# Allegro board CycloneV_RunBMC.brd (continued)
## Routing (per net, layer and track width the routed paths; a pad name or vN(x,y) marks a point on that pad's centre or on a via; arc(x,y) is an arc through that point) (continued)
RMII_NIC_BMC_CRS_R_DV: length 4
  BOTTOM w0.112: RB191.1 56.29,4.41 56.43,4.27 56.91,4.27 57.18,4.01 JT3.216
RMII_NIC_BMC_RXD_0: length 36.7
  TOP w0.127: UT7.AD12 v1(37.18,16.81)
  L3-SIG w0.076: v1(59.92,4.76) 59.12,4.76 58.64,5.24 57.85,5.24 57.52,4.91 56.31,4.91 55.62,5.6 55.62,6.12 55,6.73 55,11.34 54.13,12.21 54.13,12.81 55.24,13.92 55.24,14.23 54.61,14.86 49.59,14.86 49.29,14.56 49.29,14.48 49.14,14.33 46.06,14.33 45.06,15.33 44.11,15.33 43.25,16.19 43.25,16.46 42.49,17.23 37.6,17.23 v1(37.18,16.81) 37.19,16.81
  BOTTOM w0.112: v1(59.92,4.76) 59.32,5.36 RB173.2
RMII_NIC_BMC_RXD_1: length 31.1
  TOP w0.127: v1(40.4,10.37) 40.4,10.9 40.1,11.21 39.58,11.21 UT7.AG5
  L3-SIG w0.076: v1(40.4,10.37) 40.82,9.96 41.44,9.96 45.72,5.67 45.72,5.05 46.3,4.47 46.45,4.47 47.21,3.71 47.21,2.55 48.13,1.63 58.26,1.63 59.37,2.74 59.37,3.88 59.61,4.12 v1(60.95,4.12)
  BOTTOM w0.112: RB172.2 61.72,5.76 61.72,4.98 61.51,4.78 61.41,4.78 60.95,4.32 v1(60.95,4.12)
RMII_NIC_BMC_RXD_R_0: length 4.4
  BOTTOM w0.112: JT3.228 60.18,2.84 60.31,2.97 60.31,5.74 RB173.1
RMII_NIC_BMC_RXD_R_1: length 4.5
  BOTTOM w0.112: JT3.230 60.68,3.03 60.55,3.16 60.55,4.96 60.95,5.36 60.95,5.81 RB172.1
RST_BMC_RSTBTN_OUT_N: length 33.5
  TOP w0.127: UT7.AF7 v1(38.78,12.81)
  L8-SIG w0.076: v1(38.78,12.81) 38.78,12.33 39.94,11.16 39.94,9.46 39.73,9.24 39.33,9.24 38.41,8.32 34.88,8.32 33.42,6.87 33.03,6.87 32.19,6.03 31.5,6.03 31.08,5.61 31.08,4.55 30.14,3.61 30.14,2.75 29.61,2.22 21.48,2.22 v1(20.41,3.28)
  BOTTOM w0.089: 39.52,12.07 v1(38.78,12.81)
  BOTTOM w0.112: RB139.2 41.41,11.97 39.62,11.97 39.52,12.07 ; JT3.76 20.32,1.71 20.32,2.78 20.41,2.88 v1(20.41,3.28)
RST_EMMC_SMC_R_N: length 8
  TOP w0.104: v1(9.98,30.47) 10.46,30 12.16,30 12.49,30.33 12.49,31.78 12.69,31.98 13.1,31.98 13.62,32.5 RT12.2
  BOTTOM w0.127: UB4.M5 v1(9.98,30.47)
RST_ESPI_RESET_BMC_N: length 20.7
  TOP w0.104: v1(44.7,5.52) 44.7,5.13 44.09,4.53 44.09,3.6 44.43,3.26 JT3.165
  TOP w0.127: v1(33.98,13.59) 33.98,13.61 UT7.Y8
  L3-SIG w0.076: v1(44.7,5.52) 44.7,6.23 41.71,9.21 40.76,9.21 40.75,9.23 37.69,9.23 37.59,9.33 37.59,9.76 37.38,9.96 37.08,9.96 36.24,10.8 35.5,10.8 35.15,11.15 35.15,11.38 34.89,11.64 34.44,11.64 33.98,12.1 v1(33.98,13.59)
RST_HPS_POR_M10_N: length 94.5
  TOP w0.104: v1(1.77,33.03) 2.38,33.03 2.53,32.88 ; 2.53,32.88 2.86,33.21 3.05,33.21 3.32,33.48 R4L128.2 ; 2.53,32.88 UT1.3
  TOP w0.127: UT4.A11 v1(53.88,24.44)
  L5-SIG w0.076: v1(47.75,49.26) 48.41,48.6 48.41,48.29 50.34,46.36 50.34,38.16 50.99,37.5 50.99,33.39 51.26,33.13 53.68,33.13 53.88,32.92 v1(53.88,24.44)
  L8-SIG w0.076: v1(1.77,33.03) 0.98,33.81 0.98,48.11 1.77,48.89 4.16,48.89 4.17,48.9 47.39,48.9 v1(47.75,49.26)
RST_HPS_POR_N: length 136.3
  TOP w0.104: v1(61.74,41.56) 63.62,41.56 63.72,41.66 JT1.7 ; v1(5.23,30.48) 5.23,29.48 5.07,29.33 R4L39.2 4.21,29.33 4.08,29.21 R4L40.2 4.07,28.61 R4L29.2
  TOP w0.127: UT7.H19 v1(23.58,23.21)
  L3-SIG w0.076: v1(61.74,41.56) 61.74,43.49 61.56,43.67 61.56,46.87 60.42,48.01 6.01,48.01 3.45,45.45 3.45,26.5 3.98,25.96 4.39,25.96 5.04,25.32 6.74,25.32 7.16,25.74 7.71,25.74 8.43,25.02 12.39,25.02 14.01,23.4 18.31,23.4 18.46,23.55 21.38,23.55 21.72,23.21 v1(23.58,23.21)
  L10-SIG w0.076: v1(5.23,30.48) 5.77,31.03 8,31.03 8.4,30.63 8.4,29.57 10.14,27.83 11.49,27.83 11.73,27.59 13.36,27.59 16.69,24.26 17.87,24.26 18.51,23.63 23.16,23.63 v1(23.58,23.21)
RST_HPS_POR_R1_N: length 1.6
  TOP w0.104: R4L29.1 2.38,29.14 2.53,29.3 UT1.4
RST_HPS_POR_R_N: length 1.8
  TOP w0.104: R4L39.1 4.64,30.54 4.39,30.79 3.96,30.79 3.83,30.67 UT1.6
RST_HPS_PORBTN__R_N: length 13.6
  BOTTOM w0.508: v1(2.3,36.05) 2.84,36.58 2.84,42.93 1.34,44.43 1.34,45.98 2.63,47.27 Q6A1.1
RST_HPS_RST_M10_N: length 77.7
  TOP w0.127: v1(54.88,24.49) 54.88,24.49 54.88,25.02 UT4.A10
  L5-SIG w0.076: v1(59.38,49.18) 60.57,47.99 60.57,40.42 59.51,39.35 58.24,39.35 56.48,37.6 56.48,37.24 54.88,35.64 v1(54.88,24.49)
  L8-SIG w0.076: v1(14.88,47.15) 14.88,47.53 15.46,48.11 48.96,48.11 49.57,48.72 58.92,48.72 v1(59.38,49.18)
  BOTTOM w0.112: UB1.3 13.59,48.63 13.73,48.77 14.14,48.77 14.45,48.47 14.84,48.47 RB21.2 14.93,47.19 v1(14.88,47.15)
RST_HPS_RST_N: length 30.6
  TOP w0.089: UT7.A23 17.62,26.01
  TOP w0.104: R7A4.2 9.2,41.37 v1(9.65,41.81) 9.19,41.81 9.08,41.92 J4.10 ; v1(13.07,34.93) 14.3,34.93 14.51,34.73 RT12.1 15.26,34.12 16.48,32.9 16.48,31.07 16.78,30.76 16.78,28.76 17.27,28.28 17.27,26.24 17.5,26.01 17.62,26.01
  L8-SIG w0.076: v1(9.65,41.81) 10.15,41.31 10.15,38.51 10.46,38.21 10.46,35.16 10.68,34.93 v1(13.07,34.93)
  BOTTOM w0.112: v1(9.65,41.81) 11.49,43.66 R7A2.2 RB36.2
RST_HPS_RST_R1_N: length 1.3
  BOTTOM w0.112: UB1.6 R7A2.1
RST_HPS_RST_R2_N: length 1.3
  BOTTOM w0.112: UB1.4 RB36.1
RST_HPS_RSTBTN__R_N: length 13.9
  TOP w0.104: v1(9.59,41.18) 10,40.77 10,38.89
  BOTTOM w0.112: v1(9.59,41.18) 9.24,41.53 9.24,42.6 11.22,44.58 11.22,46.16 12.29,47.22 UB1.1 11.96,48.16 11.7,48.42 R7A1.2 10.41,48.42 10.15,48.16 Q7A1.1
RST_PERSTL1_R: length 21.1
  TOP w0.127: UT7.W15 v1(33.18,20.01)
  L5-SIG w0.076: v1(33.18,20.01) 33.57,20.4 34.94,20.4 35.17,20.17 35.17,16.39 34.36,15.58 34.36,13.12 32.8,11.56 32.8,8.62 33.03,8.39 34.18,8.39 34.77,7.8 v1(34.77,7.7)
  BOTTOM w0.089: 36.49,7.65 36.49,7.72 36.13,8.08 35.15,8.08 v1(34.77,7.7)
  BOTTOM w0.112: RB177.1 36.49,7.65
RST_PLTRST_B_N: length 6
  BOTTOM w0.112: JT3.142 36.68,2.96 36.77,3.05 36.77,3.83 38.02,5.07 RB175.2 RB177.2
RST_PLTRST_MONITOR_N: length 35.7
  TOP w0.104: v1(31.34,7.22) 27.2,7.22 26.59,6.61 26.59,4.6 26.29,4.3 26,4.3 25.43,3.72 JT3.97
  TOP w0.127: UT7.AF21 v1(38.78,24.81)
  L5-SIG w0.076: v1(38.78,24.81) 38.78,23.91 38.37,23.5 38.37,19.72 37.59,18.94 37.59,11.84 36.75,11 36.75,8.62 36.59,8.46 36.59,7.19 35.95,6.55 34.1,6.55 33.81,6.84 31.57,6.84 31.34,7.07 v1(31.34,7.22)
RST_SMC_SMB_MUX_RST_N: length 38.7
  TOP w0.089: UT7.AH14 40.44,18.81
  TOP w0.104: v1(42.72,19.16) 41.64,19.16 41.36,19.44 RT59.1 41.34,19.72 40.44,18.81 ; JT3.101 26.43,2.92 26.66,3.15 26.66,3.6 26.79,3.72 v1(27.37,3.72)
  L5-SIG w0.076: v1(42.72,19.16) 41.85,18.29 41.85,14.76 43.2,13.42 43.2,12 42.79,11.6 42.79,8.06 42.11,7.37 42.11,6.47 41.62,5.99 37.8,5.99 36.76,4.95 34.92,4.95 34.59,4.62 34.59,4.2 34.87,3.92 34.87,2.9 34.48,2.51 28.56,2.51 27.65,3.43 27.65,3.45 v1(27.37,3.72)
RST_USBPHY_RESET_N: length 45
  TOP w0.104: v1(58.39,14.25) 58.39,14.18 58.05,13.85 57.99,13.85 RT91.2 58,13.62 U8A6.27
  TOP w0.127: UT7.C6 v1(19.58,12.01)
  L10-SIG w0.076: v1(50.65,11.43) 50.27,11.43 50.23,11.38 46.17,11.38 45.03,12.52 43.75,12.52 42.64,11.41 41.55,11.41 40.94,10.8 34.59,10.8 34.38,11.01 34.38,11.38 34.18,11.59 21.43,11.59 20.57,12.45 20.02,12.45 v1(19.58,12.01)
  BOTTOM w0.112: v1(58.39,14.25) 58.23,14.41 57.07,14.41 56.66,14 55.93,14 55.29,13.37 54.8,13.37 54.79,13.37 54.73,13.37 54.3,12.93 51.86,12.93 51.61,12.68 51.61,12.5 50.92,11.82 50.92,11.7 v1(50.65,11.43)
RST_USBPHY_USB2B_RESET_N: length 56.7
  TOP w0.104: EU12.27 60.94,21.48 v1(60.95,21.49)
  TOP w0.127: UT7.E4 v1(21.18,10.41)
  L10-SIG w0.076: v1(21.18,10.41) 21.18,10.67 20.8,11.05 20.8,11.38 20.59,11.59 19.45,11.59 19.23,11.81 19.23,15.46 19.35,15.58 21.33,15.58 21.8,15.11 22.05,15.11 23.09,14.07 23.09,13.61 23.44,13.27 23.97,13.27 24.28,12.96 35.26,12.96 36.3,13.99 38.99,13.99 39.24,13.75 39.84,13.75 40.33,14.24 42.5,14.24 42.69,14.05 48.66,14.05 49.47,14.86 55.54,14.86 58.38,17.7 58.38,17.93 60.95,20.51 v1(60.95,21.49)
  BOTTOM w0.112: R411.2 v1(60.95,21.49)
SGPIO_SMC_CPLD_CLK: length 60
  TOP w0.104: v1(6.09,3.95) 6.31,3.95 6.52,3.74 6.52,3.26 6.52,3.26 6.52,3.23 5.93,2.64 JT3.19
  TOP w0.127: v1(38.81,30.45) 38.78,30.42 38.78,29.61 UT7.AF27
  L8-SIG w0.076: v1(6.09,3.95) 5.8,3.95 5.59,3.73 5.08,3.73 4.43,4.39 4.43,5.5 4.92,6 6.05,6 7.46,7.41 7.46,8.75 7.66,8.94 7.66,15.2 11.27,18.81 11.27,20.22 13.86,22.81 13.86,23.88 15.82,25.84 18.28,25.84 18.46,26.02 23.41,26.02 24.99,27.59 25.39,27.59 25.62,27.82 25.62,29.04 25.77,29.19 28.67,29.19 29.05,29.57 29.05,30.05 29.97,30.97 32.91,30.97 33.53,31.58 34.99,31.58 35.44,31.13 38.13,31.13 v1(38.81,30.45)
SGPIO_SMC_CPLD_DIN: length 56.4
  TOP w0.104: v1(5.35,4.65) 5.15,4.65 4.82,4.32 4.82,2.99 4.93,2.88 JT3.15
  TOP w0.127: v1(38.78,28.83) 38.78,28.01 UT7.AF25
  L8-SIG w0.076: v1(38.78,28.83) 38.42,29.19 31.06,29.19 30.3,28.43 29.89,28.43 29.83,28.37 29.83,28.37 29.05,27.59 26.61,27.59 26.41,27.39 26.41,26.8 24.78,25.18 24.15,25.18 24,25.02 24,24.69 23.72,24.41 18.46,24.41 18.28,24.24 15.86,24.24 11.68,20.06 11.68,18.04 11.21,17.57 11.21,16.16 10.77,15.72 10.77,14.92 9.23,13.38 9.23,11.54 9.52,11.25 9.52,8.01 9.15,7.65 8.27,7.65 7.97,7.35 7.97,5.72 7.76,5.51 5.94,5.51 5.76,5.33 5.76,4.77 5.64,4.65 v1(5.35,4.65)
SGPIO_SMC_CPLD_DOUT: length 55.8
  TOP w0.104: JT3.17 5.43,2.88 5.08,3.23 5.08,3.89 v1(5.31,4.12)
  TOP w0.127: UT7.AF28 v1(37.95,30.44)
  L8-SIG w0.076: v1(37.95,30.44) 37.53,30.03 29.79,30.03 29.38,29.62 29.38,28.91 28.9,28.43 26.54,28.43 26.36,28.25 26.36,27.82 26.16,27.62 25.85,27.62 25.57,27.34 25.57,26.75 24.75,25.93 24.19,25.93 23.97,25.71 23.97,25.48 23.7,25.2 16.54,25.2 11.47,20.14 11.47,18.73 10.37,17.62 10.37,14.81 8.65,13.09 8.65,10.78 9.27,10.16 9.27,8.05 9.07,7.85 8.19,7.85 6.06,5.72 5.12,5.72 4.83,5.42 4.83,4.61 v1(5.31,4.12)
SGPIO_SMC_CPLD_LD_N: length 61.9
  TOP w0.104: v1(4.01,4.68) 4.06,4.73 4.24,4.73 4.43,4.54 JT3.13
  TOP w0.114: UT7.AG28 39.77,30.01 40.13,30.36 40.13,31.98 39.72,32.39 36.44,32.39 v1(35.88,31.83)
  L8-SIG w0.076: v1(35.88,31.83) 35.45,32.26 33.46,32.26 32.47,31.27 29.86,31.27 28.59,30 24.9,30 24.78,29.89 24.78,27.79 23.79,26.8 21.28,26.8 21.27,26.81 16.5,26.81 13.61,23.92 13.61,22.87 11.07,20.33 11.07,18.95 6.75,14.64 6.75,9.12 6.61,8.98 6.61,6.97 5.85,6.2 4.69,6.2 4.01,5.52 v1(4.01,4.68)
SMB_BATPAK_CLK: length 38.8
  TOP w0.089: 40.73,28.71 40.44,28.41 UT7.AH26
  TOP w0.104: 40.73,28.71 40.76,28.73 41.48,28.73 41.55,28.66 RT33.1 41.52,28.69 41.52,29.27 v1(41.83,29.57) ; v1(50.37,5.41) 50.37,4.92 49.93,4.48 JT3.187
  L3-SIG w0.076: v1(41.83,29.57) 41.86,29.6 43.07,29.6 44.49,28.17 v1(48.02,28.17)
  L8-SIG w0.076: v1(48.02,28.17) 48,28.17 47.59,27.77 47.59,22.52 48.39,21.72 48.39,19.68 49.57,18.5 49.57,17.76 48.74,16.92 48.74,12.81 48.28,12.35 48.28,7.67 50.24,5.7 50.24,5.69 50.31,5.62 50.31,5.47 v1(50.37,5.41)
SMB_BATPAK_DATA: length 43.7
  TOP w0.104: v1(50.41,4.43) 50.82,4.02 50.82,3.2 50.43,2.81 JT3.189
  TOP w0.127: UT7.AC22 v1(36.4,25.63)
  L3-SIG w0.076: v1(48.05,27.62) 47.57,27.62 47.31,27.87 44.06,27.87 42.95,26.76 37.08,26.76 36.4,26.08 v1(36.4,25.63)
  L8-SIG w0.076: v1(50.41,4.43) 50.76,4.77 50.76,5.57 50.59,5.73 50.59,6.56 50.14,7.01 50.14,8.32 50.27,8.45 50.27,10.52 49.36,11.43 49.36,12.64 49.04,12.96 49.04,16.64 49.88,17.48 49.88,18.62 48.61,19.89 48.61,21.85 47.9,22.56 47.9,27.08 48.05,27.23 v1(48.05,27.62)
  BOTTOM w0.089: v1(36.4,25.63) 36.76,25.99 37.53,25.99 37.73,25.8 RT137.1
SMB_BMC2BMC_CLK: length 32.2
  TOP w0.104: v1(48.76,4.91) 48.4,4.55 48.4,4.15 48.74,3.82 48.74,3 48.43,2.69 JT3.181
  TOP w0.127: UT7.AG16 v1(39.56,20.03)
  L8-SIG w0.076: v1(47.75,20.43) 46.81,19.49 46.81,14.31 46.21,13.71 46.21,11.41 v1(46.65,10.97) 46.88,10.74 46.88,8.03 48.76,6.15 v1(48.76,4.91)
  L10-SIG w0.076: v1(39.56,20.03) 39.88,20.35 42.51,20.35 42.79,20.63 47.17,20.63 47.37,20.43 v1(47.75,20.43)
  BOTTOM w0.112: R2A21.1 47.08,11.7 46.87,11.49 46.32,11.49 46.15,11.31 RB148.1 46.64,10.98 v1(46.65,10.97)
SMB_BMC2BMC_DATA: length 32.1
  TOP w0.089: 40.73,17.56 40.33,17.56 UT7.AH12
  TOP w0.104: JT3.183 48.93,2.87 48.97,2.91 48.97,3.25 v1(49.35,3.64) ; v1(48.52,18.23) 48.52,18.17 48.06,17.71 45.57,17.71 45.14,18.14 44.57,18.14 43.99,17.56 43.33,17.56 42.98,17.2 41.52,17.2 41.26,17.47 RT70.1 40.73,17.56
  L8-SIG w0.076: v1(48.52,18.23) 48.37,18.08 48.37,12.92 48.06,12.62 48.06,12.6 47.85,12.39 47.85,11.33 47.34,10.83 47.34,8.13 49.17,6.3 49.17,4.38 49.35,4.21 v1(49.35,3.64)
  BOTTOM w0.112: R2A22.2 48.28,17.6 48.52,17.84 v1(48.52,18.23)
SMB_BMC_RSSD_7_0_CLK: length 22.5
  TOP w0.089: UT7.AG8 39.54,13.65 40.03,13.65 40.14,13.54 40.73,13.54
  TOP w0.104: v1(41.79,11.03) 41.79,11.63 41.66,11.76 41.66,13.7 41.47,13.89 RT93.1 41.23,13.89 40.89,13.54 40.73,13.54 ; JT3.123 31.93,3.11 v1(31.96,3.14)
  L8-SIG w0.076: v1(41.79,11.03) 41.83,10.99 41.83,8.69 40.71,7.57 40.26,7.57 40.18,7.65 37.62,7.65 36.05,6.08 34.59,6.08 33.6,5.09 32.66,5.09 32.35,4.77 32.35,4.34 32.37,4.32 32.37,3.55 v1(31.96,3.14)
SMB_BMC_RSSD_7_0_DATA: length 23.9
  TOP w0.104: RT114.1 32.58,5.97 v1(32.02,5.42) 32.02,5.03 32.05,5.01 32.05,4.65 32.38,4.32 32.38,3.23 32.43,3.17 JT3.125
  TOP w0.127: UT7.AG13 39.58,18.41 v1(39.59,18.41)
  L5-SIG w0.076: v1(32.02,5.42) 33.86,5.42 34.34,5.9 36.3,5.9 37.28,6.88 37.28,7.49 38.4,8.62 38.4,11.49 39.16,12.25 39.16,17.99 v1(39.59,18.41)
SMB_C5_M10_CLK: length 20.4
  TOP w0.104: UT4.H15 49.39,31.53 48.18,31.53 47.87,31.22 47.87,30.49 47.52,30.13 RT49.1 46.96,25.81 46.8,25.66 v1(45.26,25.66) ; RT68.2 43.1,18.27 43.25,18.12 v1(43.63,18.12)
  L5-SIG w0.114: v1(45.26,25.66) 45.41,25.66 45.67,25.4 45.67,23.25 43.93,21.52 43.93,18.42 v1(43.63,18.12)
SMB_C5_M10_DATA: length 2.9
  TOP w0.104: UT4.H16 46.97,32.02 RT44.2 RT47.1
SMB_C5_M10_R_CLK: length 1.4
  TOP w0.089: UT7.AH13 40.24,18.27 40.73,18.27
  TOP w0.104: 40.73,18.27 40.84,18.27 40.85,18.27 RT68.1
SMB_C5_M10_R_DATA: length 24.5
  TOP w0.104: v1(45.52,31.6) 45.66,31.6 RT44.1
  TOP w0.127: UT7.W14 v1(33.18,18.41)
  L8-SIG w0.076: v1(33.18,18.41) 33.6,18.83 35.65,18.83 36.14,19.31 38.93,19.31 39.19,19.57 39.19,20.18 39.57,20.55 40.23,20.55 41.45,21.77 44.12,21.77 45.67,23.32 45.67,31.49 45.55,31.6 v1(45.52,31.6)
SMB_HOST_LVC3_CLK: length 27.8
  TOP w0.127: UT7.U14 v1(31.58,18.41)
  L5-SIG w0.076: v1(33.29,4.53) 32.78,5.04 32.21,5.04 31.29,4.12 29.41,4.12 28.8,4.73 28.79,4.73 28.56,4.96 28.56,5.78 30.12,7.34 30.12,7.64 30.37,7.89 30.37,11.64 31.97,13.24 31.97,15.27 32.53,15.83 32.53,16.36 32.76,16.59 32.76,18.64 32.6,18.8 31.97,18.8 v1(31.58,18.41)
  BOTTOM w0.112: RB190.1 33.39,5.06 33.29,4.96 v1(33.29,4.53) 33.85,4.53 34.61,3.77 34.61,3.07 34.68,3 JT3.134
SMB_HOST_LVC3_DATA: length 25.1
  TOP w0.089: 40.73,14.38 40,14.38 39.95,14.43 v1(39.58,14.43)
  TOP w0.104: RT90.1 41.62,15.02 40.99,14.38 40.73,14.38
  TOP w0.127: UT7.AG9 39.56,14.43 v1(39.58,14.43)
  L8-SIG w0.076: v1(39.58,14.43) 39.58,13.76 39.97,13.37 41.32,13.37 41.52,13.16 41.52,11.39 41.41,11.27 41.41,10.82 41.59,10.63 41.59,8.99 v1(40.56,7.96)
  BOTTOM w0.112: v1(40.56,7.96) 40.06,7.96 39.67,8.34 34.69,8.34 34.41,8.05 34.41,7.7 33.95,7.24 33.95,6.56 34.26,6.26 34.26,4.47 34.37,4.35 34.37,4.35 34.85,3.87 34.85,3.21 35.18,2.88 JT3.136
SMB_HSBP_LVC3_CLK: length 35.6
  TOP w0.089: 40.73,14.84 v1(40.58,14.84) 40.55,14.81 UT7.AH9
  TOP w0.104: RT88.1 41.29,15.52 41.12,15.36 41.12,15.01 40.96,14.84 40.73,14.84
  L8-SIG w0.076: v1(16.63,3.58) 17.02,3.58 17.04,3.6 19.28,3.6 20.02,4.34 20.45,4.34 20.91,4.79 20.91,5.15 21.12,5.36 21.65,5.36 23.87,7.57 24.71,7.57 26.36,9.23 28.7,9.23 29.44,9.97 30.13,9.97 30.42,10.26 30.42,10.56 30.63,10.77 30.91,10.77 31.16,11.02 31.16,11.33 32.38,12.55 33.09,12.55 33.67,13.13 34.03,13.13 36.39,15.49 36.39,16.08 36.68,16.37 39.84,16.37 40.07,16.13 40.07,15.35 v1(40.58,14.84)
  BOTTOM w0.112: JT3.60 16.18,2.75 16.63,3.2 v1(16.63,3.58)
SMB_HSBP_LVC3_DATA: length 42.3
  TOP w0.127: UT7.AE15 v1(37.98,20.01)
  L8-SIG w0.076: v1(37.98,20.01) 37.41,20.58 36.11,20.58 35.81,20.27 35.81,19.82 35.31,19.32 31.81,19.32 31.16,18.67 31.16,15.02 30.91,14.77 30.63,14.77 30.37,14.51 30.37,14.2 30.14,13.98 29.76,13.98 29.41,13.62 29.41,13.49 28.7,12.78 22.62,12.78 22.22,12.38 19.43,12.38 19.22,12.16 19.22,8.73 18.9,8.41 18.43,8.41 16.81,6.79 16.81,6.05 v1(16.17,5.42)
  BOTTOM w0.089: v1(37.98,20.01) 38.35,20.38 40.61,20.38 40.73,20.26 40.73,20.12 40.73,20.12
  BOTTOM w0.112: JT3.62 16.68,2.9 16.94,3.16 16.94,3.28 17.21,3.56 17.21,4.2 16.73,4.68 16.53,4.68 16.17,5.03 v1(16.17,5.42) ; RB106.1 40.85,19.84 40.76,19.93 40.76,20.09 40.73,20.12
SMB_INTERNAL_CLK: length 165.1
  TOP w0.104: EUT2.3 5.88,8.12 v1(6.22,7.79) ; EUT3.23 14.48,11.14 14.45,11.18 v1(14.45,11.25) ; JT1.5 62.45,44.98 62.24,45.19 v1(61.99,45.19) ; v1(11.42,12.37) 11.69,12.1 12.22,12.1 12.31,12.19 EUT1.19 ; v1(45.74,15.7) 45.74,14.46 45.64,14.36 45.23,14.36 RT92.1 45.15,14.28 R434.1
  L5-SIG w0.076: v1(11.42,12.37) 12.41,11.38 12.41,11.21 12.77,10.86 14.06,10.86 v1(14.45,11.25)
  L5-SIG w0.114: v1(45.74,15.7) 45.99,15.96 45.99,18.43 v1(44.65,19.77)
  L8-SIG w0.076: v1(44.65,19.77) 44.65,20.68 46.45,22.48 46.45,27.95 49.68,31.17 49.68,39.15 50.56,40.04 59.86,40.04 60.37,40.54 60.37,41.33 61.99,42.96 v1(61.99,45.19) 61.99,45.93 61.74,46.18 50.64,46.18 49.4,44.94 44.9,44.94 44.39,45.45 44.39,46.36 43.68,47.07 16.55,47.07 15.28,45.81 15.28,33.18 16.17,32.29 16.17,31.43 16.78,30.82 16.78,30.29 16.4,29.91 16.4,27.1 13.4,24.1 13.4,23.09 12.29,21.98 7.33,21.98 5.77,20.41 5.77,15.41 4.29,13.92 4.29,9.53 5.66,8.16 5.84,8.16 v1(6.22,7.79)
  L10-SIG w0.076: v1(11.42,12.37) 10.89,12.37 9.87,11.36 9.87,9.77 9.15,9.05 8.09,9.05 7.82,9.32 6.97,9.32 6.22,8.57 v1(6.22,7.79)
  BOTTOM w0.112: v1(44.65,19.77) 44.65,20.74 43.81,21.57 42.72,21.57 42.61,21.47 RB98.2
SMB_INTERNAL_CLK_R2: length 3.7
  TOP w0.104: EU5C1.4 48.49,11.89 48.15,12.22 47.92,12.22 47.8,12.35 47.39,12.35 47.01,12.73 47.01,12.74 46.61,13.14 46.42,13.14 R434.2
SMB_INTERNAL_DATA: length 166.4
  TOP w0.104: v1(62.45,45.52) JT1.6 ; R435.1 RT97.1 RT95.2 46.22,12.68 46.32,12.58 v1(46.63,12.58) ; EUT3.22 14.88,11.1 15.02,11.23 v1(15.02,11.24) ; EUT1.20 12.81,12.19 12.45,11.84 v1(11.4,11.84) ; EUT2.2 5.23,8.07 5.52,7.78 v1(5.68,7.78)
  L5-SIG w0.076: v1(11.4,11.84) 12.62,10.62 14.39,10.62 v1(15.02,11.24)
  L8-SIG w0.076: v1(46.63,12.58) 46.63,12.95 46.6,12.98 46.6,13.11 47.13,13.64 47.13,19.2 48.13,20.2 48.13,21.65 47.29,22.48 47.29,28.33 49.96,30.99 49.96,38.28 50.72,39.05 59.45,39.05 60.7,40.29 60.7,41.2 62.45,42.96 v1(62.45,45.52) 62.45,45.76 61.83,46.39 50.56,46.39 49.34,45.17 45,45.17 44.62,45.55 44.62,46.44 43.78,47.27 16.46,47.27 15.08,45.9 15.08,33.08 15.97,32.19 15.97,31.35 16.58,30.74 16.58,30.37 16.2,29.99 16.2,27.18 13.2,24.19 13.2,23.18 12.2,22.18 7.25,22.18 5.57,20.5 5.57,15.5 4.06,13.98 4.06,9.47 5.68,7.85 v1(5.68,7.78)
  L10-SIG w0.076: v1(5.68,7.78) 5.66,7.8 5.66,8.35 6.87,9.57 8,9.57 8.27,9.3 9.05,9.3 9.59,9.84 9.59,11.37 10.98,12.76 11.72,12.76 11.83,12.65 11.83,11.97 11.7,11.84 v1(11.4,11.84)
SMB_INTERNAL_DATA_R2: length 1
  TOP w0.104: EU5C1.5 47.6,11.35 47.49,11.46 R435.2
SMB_INTERNAL_R_CLK: length 3.3
  TOP w0.127: UT7.AF17 v1(38.78,21.61)
  BOTTOM w0.089: 40.73,21.19 39.41,21.19 39,21.61 v1(38.78,21.61)
  BOTTOM w0.112: RB98.1 41.01,21.47 40.73,21.19
SMB_INTERNAL_R_DATA: length 18.9
  TOP w0.104: v1(44.98,17.76) 44.98,17.3 45.01,17.27 45.01,16.19 44.68,15.86 44.68,13.11 RT95.1
  TOP w0.127: UT7.V13 v1(32.38,17.61)
  L3-SIG w0.076: v1(44.98,17.76) 44.6,17.76 44.58,17.73 43.38,17.73 43.08,18.03 42,18.03 41.98,18.01 33.04,18.01 32.63,17.61 v1(32.38,17.61)
SMB_IPMB_LVC3_CLK: length 18.1
  TOP w0.127: v1(40.35,12.81) 39.98,13.18 UT7.AH7
  L5-SIG w0.076: v1(32.76,3.92) 33.22,3.92 33.68,4.37 33.68,4.89 34.43,5.64 36.38,5.64 37.54,6.8 37.54,7.4 39.19,9.05 39.19,11.64 v1(40.35,12.81)
  BOTTOM w0.089: 40.73,12.43 v1(40.35,12.81)
  BOTTOM w0.112: JT3.128 33.18,3.81 33.07,3.92 v1(32.76,3.92) ; RB138.1 40.79,12.38 40.73,12.43
SMB_IPMB_LVC3_DATA: length 28.5
  TOP w0.127: UT7.AF13 38.78,18.41 v1(38.8,18.41)
  L5-SIG w0.076: v1(34.15,3.69) 34.15,3.74 33.92,3.98 33.92,4.79 34.54,5.42 36.53,5.42 37.78,6.67 37.78,7.19 38.47,7.88 39.34,7.88 39.97,8.51 39.97,11.79 40.4,12.22 40.99,12.22 41.34,12.58 41.34,13.06 41.07,13.34 40.43,13.34 40.02,13.75 40.02,18.65 39.77,18.9 39.29,18.9 v1(38.8,18.41)
  BOTTOM w0.089: 40.73,17.46 40.25,17.46 40,17.71 39.5,17.71 v1(38.8,18.41)
  BOTTOM w0.112: 40.73,17.46 RB116.1 ; JT3.130 33.68,3.6 33.75,3.66 34.13,3.66 v1(34.15,3.69)
SMB_PCIE_LVC3_CLK: length 57.5
  TOP w0.104: v1(53.59,4.93) 53.97,4.55 53.97,3.44 54.43,2.98 JT3.205
  TOP w0.127: UT7.U13 v1(31.58,17.61)
  L3-SIG w0.076: v1(31.58,17.61) 32,17.19 32,16.57 32.15,16.41 34.84,16.41 36.4,14.86 39.88,14.86 40.2,15.18 41.03,15.18 42.3,13.91 44.48,13.91 45.1,13.29 50.13,13.29 50.46,13.62 51.45,13.62 51.59,13.48 51.59,11.27 51.2,10.88 51.2,8.95 49.37,7.12 49.37,4.7 49.8,4.27 49.8,3.03 49.9,2.93 51.56,2.93 51.81,3.18 51.81,4.83 52.14,5.16 52.98,5.16 53.21,4.93 v1(53.59,4.93)
  BOTTOM w0.089: v1(31.58,17.61) 31.93,17.96 33.22,17.96 33.53,18.26 33.53,20.05 33.83,20.36 34.92,20.36 35.67,19.61 37.28,19.61 37.61,19.95 37.61,20.13 37.9,20.43 38.09,20.43 38.37,20.71 38.37,20.9 38.63,21.16 39.09,21.16 39.57,20.68 40.73,20.68
  BOTTOM w0.112: 40.73,20.68 40.79,20.68 41.08,20.39 RB102.1
SMB_PCIE_LVC3_DATA: length 31.1
  TOP w0.104: JT3.207 54.93,2.8 54.2,3.53 54.2,4.58 v1(54.55,4.93)
  TOP w0.127: UT7.AH8 40.19,14.01 40.25,13.95 40.46,13.95 40.5,13.9 40.52,13.9 v1(40.53,13.9)
  L3-SIG w0.089: v1(54.16,13.36) 54.16,13.38
  L5-SIG w0.076: v1(54.55,4.93) 54.17,5.32 54.17,6.08 53.47,6.78 53.47,10.2 53.18,10.5 53.18,12.38 v1(54.16,13.36)
  L10-SIG w0.076: v1(40.53,13.9) 40.9,13.9 41.03,13.77 49.6,13.77 50.41,14.59 52.91,14.59 54.14,13.36 v1(54.16,13.36)
  BOTTOM w0.089: 40.73,13.69 v1(40.53,13.9)
  BOTTOM w0.112: 40.73,13.69 40.82,13.61 RB133.1
SMB_PMBUS_LVC3_CLK: length 44.9
  TOP w0.104: JT3.47 12.93,4.14 13.26,4.48 13.45,4.48 v1(13.46,4.49)
  TOP w0.127: UT7.Y13 v1(33.98,17.61)
  L8-SIG w0.076: v1(13.46,4.49) 13.48,4.51 13.48,4.69 13.6,4.81 15.51,4.81 15.72,4.6 16.72,4.6 17.28,5.16 18.07,5.16 18.55,5.65 18.55,6.59 18.85,6.89 20.44,6.89 20.75,7.19 20.75,10.62 20.95,10.83 23.36,10.83 24.61,12.07 29.23,12.07 30.12,12.96 30.96,12.96 31.16,13.16 31.16,13.77 31.74,14.36 31.74,15.05 32.28,15.58 32.28,16.09 32.8,16.62 32.8,17 33.03,17.23 33.6,17.23 v1(33.98,17.61)
  BOTTOM w0.112: v1(33.98,17.61) 34.38,18.01 34.92,18.01 36.26,19.36 40.28,19.36 40.86,18.77 42.55,18.77 42.56,18.77 42.94,18.77 43.1,18.93 43.1,19.32 43.1,19.32 43.1,19.55 43,19.65 RB104.1
SMB_PMBUS_LVC3_DATA: length 38.8
  TOP w0.104: v1(13.42,3.92) 13.42,3.54 13.23,3.35 13.23,2.9 13.43,2.7 JT3.49 ; RT72.1 40.73,16.62 40.11,15.99 v1(39.6,15.99) UT7.AG11
  L8-SIG w0.076: v1(13.42,3.92) 13.42,3.9 13.68,3.64 14.87,3.64 15.19,3.32 15.19,3.12 15.63,2.69 18.88,2.69 20.14,3.94 21.06,3.94 22.04,4.92 22.04,5.41 23.8,7.17 24.89,7.17 26.16,8.45 27.73,8.45 29.03,8.45 29.83,9.25 30.13,9.25 31.22,10.33 31.22,10.56 31.43,10.77 31.69,10.77 31.95,11.03 31.95,11.44 32.66,12.15 33.06,12.15 33.8,12.89 34.9,12.89 35.59,13.57 35.59,14.31 36.86,15.57 39.18,15.57 v1(39.6,15.99)
SMB_RSSD_15_8_CLK: length 53.3
  TOP w0.089: 40.73,29.67 40.44,29.67 UT7.AH27
  TOP w0.104: 40.73,29.67 v1(41.12,29.67) 41.32,29.67 41.55,29.9 RT23.1
  L8-SIG w0.076: v1(41.12,29.67) 41.47,29.32 41.47,28.2 41.23,27.96 40.8,27.96 40.74,28.02 38.8,28.02 38.42,27.63 36.22,27.63 36.01,27.43 36.01,26.98 35.81,26.78 35.44,26.78 35.15,26.49 35.15,26.19 34.65,25.7 27.74,25.7 27.2,25.15 27.2,24.57 27.02,24.39 26.51,24.39 25.57,23.44 25.57,19.79 25.11,19.33 23.29,19.33 20.41,16.46 20.16,16.46 19.96,16.26 19.96,15.78 19.81,15.63 18.95,15.63 18.89,15.56 17.53,15.56 17.24,15.27 17.24,12.83 15.72,11.31 15.72,9.44 15.35,9.08 15.35,7.54 14.75,6.94 13.48,6.94 12.91,6.37 12.91,3.77 13.56,3.13 v1(13.66,3.13)
  BOTTOM w0.112: JT3.50 13.65,1.6 13.65,3.12 v1(13.66,3.13)
SMB_RSSD_15_8_DATA: length 52.8
  TOP w0.104: RT35.1 41.22,28.15 41.07,28.3 v1(41.07,28.35)
  TOP w0.127: UT7.AG25 39.55,27.98 40.7,27.98 v1(41.07,28.35)
  L8-SIG w0.076: v1(41.07,28.35) 38.13,28.35 38.11,28.37 35.85,28.37 35.17,27.69 35.17,27.01 34.97,26.81 33.02,26.81 32.78,26.57 32.78,26.2 32.51,25.92 27.1,25.92 26.34,25.16 26.34,24.64 25.27,23.58 25.01,23.58 24.78,23.35 24.78,19.86 24.48,19.55 23.22,19.55 20.61,16.93 20.21,16.93 19.73,16.45 17.42,16.45 15.97,15.01 15.97,13.82 15.44,13.29 15.44,10.98 14.75,10.29 13.21,10.29 12.24,9.33 12.24,7.31 12.52,7.04 12.52,5.52 12.37,5.37 v1(12.37,4.98)
  BOTTOM w0.112: JT3.48 13.18,3.58 13.17,3.6 13.17,3.61 13.02,3.75 13.02,4.33 v1(12.37,4.98)
SMB_SENSOR_FRU_CLK: length 2.3
  BOTTOM w0.112: R2A21.2 46.2,12.78 46.52,13.1 UB5.6
SMB_SENSOR_FRU_DAT: length 1.9
  BOTTOM w0.112: R2A22.1 47.28,13.24 47.17,13.35 UB5.5
SMB_SMLINK0_LVC3_CLK: length 45.3
  TOP w0.089: v1(39.58,15.21) 40.68,15.21 40.73,15.27
  TOP w0.104: RT86.1 41.32,16.06 40.89,15.63 40.89,15.42 40.73,15.27
  TOP w0.127: UT7.AG10 v1(39.58,15.21)
  L8-SIG w0.076: v1(39.58,15.21) 40.1,14.69 40.1,14.55 40.21,14.43 40.81,14.43 41.85,13.39 41.85,11.89 42.69,11.05 42.69,8.64 41.98,7.93 41.41,7.93 40.75,7.27 40.15,7.27 40,7.42 37.86,7.42 36.23,5.8 34.72,5.8 33.94,5.02 33.94,4.42 33.18,3.66 33.18,2.76 32.39,1.97 15.58,1.97 14.8,2.75 v1(14.8,3.16)
  BOTTOM w0.112: JT3.54 14.68,3.03 v1(14.8,3.16)
SMB_SMLINK0_LVC3_DATA: length 42.3
  TOP w0.127: UT7.AF15 v1(38.78,20.01)
  L8-SIG w0.076: v1(38.78,20.01) 38.36,19.59 35.99,19.59 35.45,19.06 32.23,19.06 32,18.83 32,15.86 31.51,15.37 31.51,14.56 30.96,14 30.63,14 30.42,13.79 30.42,13.51 30.14,13.24 29.74,13.24 28.92,12.43 24.56,12.43 23.73,11.6 20.13,11.6 19.96,11.44 19.96,7.5 19.75,7.3 17.71,7.3 17.06,6.64 17.06,5.31 16.61,4.86 15.87,4.86 15.43,5.29 v1(15.39,5.29)
  BOTTOM w0.089: 40.73,19.33 40.43,19.64 39.15,19.64 v1(38.78,20.01)
  BOTTOM w0.112: v1(15.39,5.29) 15.36,5.26 15.36,4.96 15.44,4.88 15.44,3.71 15.21,3.49 15.21,2.92 15.18,2.89 JT3.56 ; 40.73,19.33 RB109.1
SMB_SW2BMC_CLK_DBG_HOOK8: length 29
  TOP w0.089: UT7.D12 21.18,17.61 22.24,17.61 23.01,16.85 23.01,15.35 v1(22.85,15.19)
  TOP w0.104: JT3.135 34.93,2.88 34.73,3.08 34.73,3.08 34.66,3.15 34.66,3.16 34.63,3.19 34.63,3.68 34.99,4.05 35.51,4.05 35.6,4.14 v1(35.6,4.53) 35.6,4.9 35.44,5.06 35.43,5.06 35.15,5.34 RT135.1
  L3-SIG w0.076: v1(22.85,15.19) 22.9,15.19 23.3,14.79 23.69,14.79 23.95,14.53 23.95,14.35 24.27,14.03 24.45,14.03 24.76,13.72 24.76,13.53 25.1,13.19 27.83,13.19 29.33,11.69 29.33,7.93 30.91,6.36 31.64,6.36 32.76,5.24 35.27,5.24 35.6,4.9 v1(35.6,4.53)
SMB_SW2BMC_DATA_DBG_HOOK9: length 32
  TOP w0.089: UT7.C12 20.37,16.82 21.84,16.82 22.57,16.08 v1(22.57,15.93)
  TOP w0.104: JT3.137 35.43,2.71 34.89,3.25 34.89,3.26 34.87,3.28 34.87,3.57 35.12,3.82 35.84,3.82 36.14,4.12 v1(36.14,4.5) 36.14,4.98 35.78,5.34 RT136.1
  L3-SIG w0.076: v1(22.57,15.93) 22.57,15.55 22.5,15.47 22.5,14.86 23.34,14.03 23.65,14.03 23.95,13.74 23.95,13.55 24.71,12.78 27.4,12.78 28.87,11.31 28.87,7.04 29.69,6.23 29.69,4.44 29.88,4.24 31.68,4.24 32.35,4.91 33.5,4.91 34.38,4.02 35.65,4.02 v1(36.14,4.5)
SMB_TEMP_SENSOR_LVC3_CLK: length 50.9
  TOP w0.104: JT3.53 14.43,2.88 14.42,2.89 14.42,3.57 14.42,3.57 v1(14.42,4.15) ; v1(43.69,16.35) 43.62,16.28 43.62,16.1 43.62,16.1 43.62,14.4 43.29,14.07 UT10.2
  TOP w0.127: UT7.AA13 v1(34.78,17.61)
  L8-SIG w0.076: v1(34.78,17.61) 34.38,17.22 34.38,16.7 34.1,16.41 32.96,16.41 32.76,16.21 32.76,14.99 32.56,14.79 32.18,14.79 31.97,14.58 31.97,13.44 31.27,12.74 30.46,12.74 29.48,11.77 25.06,11.77 24.74,11.44 24.74,11.06 24.45,10.77 24.23,10.77 24.02,10.56 24.02,10.31 23.67,9.97 21.83,9.97 21.54,9.68 21.54,7.51 20.47,6.43 20.02,6.43 17.91,4.32 15.39,4.32 15.18,4.53 14.79,4.53 v1(14.42,4.15)
  BOTTOM w0.112: v1(43.69,16.35) 43.94,16.59 44.27,16.59 44.57,16.9 44.57,18.4 44.14,18.83 44.14,19.44 43.87,19.7 RB105.1 43.38,19.5 43.38,18.73 43.15,18.5 40.68,18.5 40.65,18.54 40.64,18.54 40.61,18.56 40.59,18.56 40.04,19.11 36.34,19.11 34.84,17.61 v1(34.78,17.61)
SMB_TEMP_SENSOR_LVC3_DATA: length 48.1
  TOP w0.089: UT7.AH11 40.54,16.97 40.73,16.97
  TOP w0.104: JT3.55 14.93,2.74 15.19,3 15.19,3.54 15,3.72 v1(15,4.1) ; 40.73,16.97 42.97,16.97 43.19,16.74 43.45,16.74 43.45,16.74 44.15,16.74 v1(44.58,16.31) 44.44,16.16 44.44,15 44.21,14.78 RT89.1 43.94,14.68 UT10.1
  L8-SIG w0.076: v1(15,4.1) 15.26,4.1 15.29,4.08 16.68,4.08 16.84,3.92 19.26,3.92 19.91,4.56 19.91,5.06 20.16,5.31 20.69,5.31 21.08,5.7 21.48,5.7 24.22,8.44 24.68,8.44 26.23,9.99 28.82,9.99 29.61,10.78 30.22,10.78 30.35,10.9 30.35,11.46 30.73,11.84 31.21,11.84 32.18,12.81 32.87,12.81 33.53,13.47 33.53,13.75 33.83,14.05 34.13,14.05 34.38,14.31 34.38,14.55 34.63,14.79 34.97,14.79 36.14,15.96 36.14,16.67 36.65,17.18 40.27,17.18 40.7,16.74 43.44,16.74 43.45,16.74 44.16,16.74 v1(44.58,16.31)
SP_BMC_UART0_RXD: length 132.1
  TOP w0.104: JT1.2 59.91,49.18 v1(59.96,49.23) ; RT106.2 6.93,6.85 6.93,4.37 7.21,4.09 v1(7.21,3.89) 6.9,3.89 6.8,3.79 6.8,3.15 6.43,2.77 JT3.21
  TOP w0.127: v1(16.81,22.54) 17.45,23.18 18.81,23.18 UT7.B19
  L3-SIG w0.076: v1(59.96,49.23) 59.18,48.44 5.68,48.44 3.02,45.78 3.02,24.49 3.42,24.08 4.48,24.08 5.23,23.34 5.23,22.71 5.63,22.31 13.79,22.31 14.37,22.89 15.84,22.89 16.2,22.54 v1(16.81,22.54)
  L5-SIG w0.076: v1(7.21,3.89) 7.21,4.12 6.85,4.48 6.85,5.36 5.27,6.95 5.27,8.56 5.58,8.87 5.58,9.68 6.24,10.34 6.47,10.34 6.83,10.7 6.83,14.36 13.66,21.19 13.66,22.33 14.04,22.71 15.94,22.71 16.12,22.54 v1(16.81,22.54)
SP_BMC_UART0_TXD: length 144
  TOP w0.104: v1(57.45,49.18) 57.45,46.87 58.87,45.44 58.87,42.24 59.07,42.04 59.58,42.04 59.91,42.37 JT1.1 ; v1(7.31,4.68) 7.31,4.37 7.64,4.04 7.64,3.25 7.34,2.95 7.03,2.95 6.93,2.85 JT3.23
  TOP w0.114: RT107.2 7.79,6.36 7.79,6.36 7.79,5.62 7.31,5.14 v1(7.31,4.68)
  TOP w0.127: UT7.C16 v1(19.58,20.81)
  L3-SIG w0.076: v1(19.58,20.81) 19.96,21.19 19.96,22.56 19.69,22.83 19.36,22.83 19.2,22.99 17.93,22.99 17.77,22.84 17.77,22.38 17.53,22.14 16.08,22.14 15.64,22.59 14.57,22.59 14.04,22.05 5.02,22.05 3.95,23.13 3.95,23.58 3.7,23.82 3.02,23.82 1.02,25.82 1.02,46.58 3.11,48.67 55.59,48.67 55.59,48.67 56.94,48.67 v1(57.45,49.18)
  L5-SIG w0.076: v1(7.31,4.68) 7.31,5.33 6.7,5.95 6.7,9.2 7.13,9.63 7.13,14.27 13.75,20.88 15.87,20.88 16.2,20.55 17.26,20.55 17.54,20.83 19.55,20.83 v1(19.58,20.81)
SP_BMC_UART1_RXD: length 132.6
  TOP w0.104: JT1.4 v1(61.18,49.26) ; JT3.41 11.43,2.93 10.98,3.38 10.98,4.48 10.29,5.18 10.29,6.98 8.6,8.67 v1(8.43,8.67)
  TOP w0.127: UT7.C19 v1(19.58,23.21)
  L3-SIG w0.076: v1(61.18,49.26) 61.18,48.88 60.54,48.24 5.89,48.24 3.23,45.59 3.23,24.76 3.62,24.37 4.79,24.37 5.56,23.6 5.56,22.81 5.78,22.59 13.48,22.59 14.09,23.2 19.57,23.2 v1(19.58,23.21)
  L5-SIG w0.076: v1(19.58,23.21) 19.98,22.8 19.98,19.77 19.27,19.06 13.96,19.06 13.38,18.47 13.38,17.23 10.48,14.33 10.48,12.02 9.75,11.28 9.75,9.99 v1(8.43,8.67)
  BOTTOM w0.112: v1(8.43,8.67) 7.85,8.67 RB158.2
SP_BMC_UART1_TXD: length 135.4
  TOP w0.089: UT7.B16 18.8,20.78 17.62,20.78
  TOP w0.104: v1(8.44,10.44) 8.45,10.44 8.55,10.34 8.58,10.34 8.9,10.03 RT100.2 9.11,10.01 9.85,9.28 9.85,7.96 10.84,6.97 11.07,6.97 11.8,6.23 11.8,3.36 11.93,3.23 JT3.43 ; 17.47,20.78 17.62,20.78 ; v1(56.89,49.18) 57.16,48.91 57.16,46.78 58.64,45.29 58.64,42.12 59.1,41.66 61.08,41.66 61.18,41.76 JT1.3
  TOP w0.114: 17.47,20.78 16.86,20.17 16.3,20.17 15.98,20.49 v1(15.59,20.49)
  L3-SIG w0.076: v1(56.89,49.18) 56.6,48.89 55.5,48.89 55.5,48.88 3.02,48.88 0.81,46.67 0.81,25.46 4.51,21.75 10.43,21.75 11.69,20.49 v1(15.59,20.49)
  L5-SIG w0.076: v1(8.44,10.44) 8.65,10.66 8.65,12.8 13.13,17.27 13.13,18.62 14.27,19.77 14.86,19.77 v1(15.59,20.49)
SPI_M10_FLASH_CLK: length 35.6
  L5-SIG w0.076: v1(63.82,45.52) 63.82,45.93 64.08,46.18 65.78,46.18 66.72,45.24 66.72,38 67.76,36.96 67.76,34.33 v1(67.37,33.94) 68.32,32.99 68.32,24.06 v1(67.94,23.68)
  BOTTOM w0.112: v1(63.82,45.52) EUB1.6 ; v1(67.94,23.68) 67.2,23.68 66.6,23.08 61.81,23.08 61.49,23.4 RB111.1 ; TP4.1 67.58,34.19 67.37,33.98 v1(67.37,33.94)
SPI_M10_FLASH_CLK_R: length 1.6
  TOP w0.127: UT4.B4 61.22,25.68 v1(61.22,25.5)
  BOTTOM w0.112: v1(61.22,25.5) 61.49,25.23 RB111.2
SPI_M10_FLASH_CS0__RN: length 1.6
  TOP w0.127: UT4.B3 v1(62.36,25.54)
  BOTTOM w0.112: RB107.2 62.64,25.81 v1(62.36,25.54)
SPI_M10_FLASH_CS0_N: length 22.8
  TOP w0.104: v1(67.37,34.6) 67.37,34.48 67.65,34.19 TP3.1
  L8-SIG w0.076: v1(68.55,37.6) 68.04,37.09 68.04,35.27 v1(67.37,34.6) 68.02,33.94 68.02,24.96 v1(67.4,24.34)
  BOTTOM w0.112: v1(68.55,37.6) RB38.2 EUB1.1
  BOTTOM w0.114: v1(67.4,24.34) 65.55,26.2 64.42,26.2 RB107.1
SPI_M10_FLASH_IO2_WP_N: length 21
  L5-SIG w0.076: v1(57.14,23.86) 56.53,24.47 56.53,30.74 56.91,31.12 56.91,32.45 58.02,33.56 58.02,35.63 59.86,37.47 v1(63.37,37.47)
  BOTTOM w0.112: v1(57.14,23.86) 57.21,23.79 RB110.1 ; v1(63.37,37.47) 63.49,37.6 RB29.2 EUB1.3
SPI_M10_FLASH_IO2_WP_R_N: length 1.8
  TOP w0.127: UT4.B7 v1(58.38,25.52)
  BOTTOM w0.112: v1(58.38,25.52) 57.88,25.02 RB110.2
SPI_M10_FLASH_IO3_HD_N: length 31.4
  L5-SIG w0.076: v1(65.09,45.52) 65.09,39.86 64.34,39.11 59.65,39.11 58.08,37.55 58.08,36.77 57.13,35.82 57.13,35.58 56.48,34.93 56.48,31.35 55.75,30.61 55.75,23.84 v1(56.18,23.41)
  BOTTOM w0.112: v1(56.18,23.41) 56.38,23.61 RB100.1 ; v1(65.09,45.52) EUB1.7 65.09,47 65.22,47.12 RB35.2
SPI_M10_FLASH_IO3_HD_R_N: length 2.2
  TOP w0.127: UT4.B9 v1(55.38,25.52)
  BOTTOM w0.112: v1(55.38,25.52) 56.22,25.52 56.38,25.35 RB100.2
SPI_M10_FLASH_MISO: length 27.7
  TOP w0.104: TP5.1 67.54,32.92 v1(67.37,32.75)
  L10-SIG w0.076: v1(65.27,37.65) 65.83,37.09 65.83,33.43 66.52,32.75 v1(67.37,32.75)
  L10-SIG w0.089: v1(68.07,23.04) 68.32,23.3 68.32,32.24 67.82,32.75 v1(67.37,32.75)
  BOTTOM w0.112: EUB1.2 65.27,38.41 v1(65.27,37.65) ; v1(68.07,23.04) 67.62,22.6 61.19,22.6 60.6,23.2 60.04,23.2 59.91,23.32 RB115.1
SPI_M10_FLASH_MISO_R: length 1.9
  TOP w0.127: UT4.B6 v1(59.38,25.52)
  BOTTOM w0.112: RB115.2 59.91,25.15 59.54,25.52 v1(59.38,25.52)
SPI_M10_FLASH_MOSI: length 34.9
  L5-SIG w0.076: v1(67.37,33.33) 67.99,32.71 67.99,24.36 67.46,23.83 v1(67.46,23.09)
  L8-SIG w0.076: v1(67.37,33.33) 66.23,33.33 65.83,33.73 65.83,41.99 63.06,44.76 v1(63.06,45.57)
  BOTTOM w0.112: TP6.1 68.12,32.92 67.71,33.33 v1(67.37,33.33) ; v1(67.46,23.09) 67.2,22.84 61.36,22.84 60.7,23.5 RB118.1 ; EUB1.5 62.55,46.21 63.06,45.7 v1(63.06,45.57)
SPI_M10_FLASH_MOSI_R: length 1.7
  TOP w0.127: UT4.B5 v1(60.38,25.52)
  BOTTOM w0.112: v1(60.38,25.52) 60.7,25.2 RB118.2
SPI_PCH_SNIFF_CLK: length 33
  TOP w0.127: v1(51.45,24.36) 51.45,24.54 51.88,24.97 UT4.A13
  L8-SIG w0.076: v1(51.45,24.36) 51.8,24.01 51.8,22.26 52.6,21.47 53.41,21.47 53.77,21.11 53.77,20.66 51.28,18.17 51.28,15.75 52.18,14.85 52.18,13.12 53.28,12.02 53.28,8.79 52.8,8.31 52.8,6.03 51.86,5.09 51.86,3.03 52.16,2.72 54.43,2.72 v1(55.62,3.92)
  BOTTOM w0.112: v1(55.62,3.92) 55.52,3.92 55.27,3.67 55.27,3.37 55.18,3.27 JT3.208
SPI_PCH_SNIFF_CS0_N: length 29.5
  TOP w0.127: UT4.C13 v1(51.38,26.52)
  L8-SIG w0.076: v1(53.58,4.32) 54.12,4.86 54.12,7.33 54.9,8.11 54.9,11.78 55.6,12.48 55.6,21.26 55.19,21.67 55.19,23.58 54.45,24.31 54.45,24.75 54.2,25 53.28,25 52.93,25.35 52.92,25.35 52.92,25.52 52.45,25.99 51.91,25.99 v1(51.38,26.52)
  BOTTOM w0.112: JT3.198 52.68,2.71 52.94,2.97 52.94,3 52.95,3.01 52.95,3.49 53.58,4.13 v1(53.58,4.32)
SPI_PCH_SNIFF_CS1_N: length 31.5
  TOP w0.127: UT4.E10 v1(54.38,28.52)
  L8-SIG w0.076: v1(54.38,28.52) 54.74,28.16 54.74,27.09 57.52,24.31 57.52,22.36 56.53,21.37 56.53,15.31 56.96,14.88 56.96,14.83 56.97,14.82 56.97,12.86 57.68,12.14 57.68,11.39 56.64,10.34 56.64,8.59 55.96,7.92 55.96,5 56.66,4.3 v1(56.66,3.84)
  BOTTOM w0.112: v1(56.66,3.84) 56.28,3.84 56.08,3.64 56.08,3.21 55.68,2.81 JT3.210
SPI_PCH_SNIFF_IO0: length 28.1
  TOP w0.127: v1(53.94,23.42) 53.51,23.86 51.03,23.86 50.88,24.01 UT4.A14
  L8-SIG w0.076: v1(53.56,5.52) 53.72,5.68 53.72,8.13 54.3,8.71 54.31,8.71 54.57,8.97 54.57,11.94 55.36,12.73 55.36,20.54 54.07,21.82 54.07,22.79 53.94,22.91 v1(53.94,23.42)
  BOTTOM w0.112: JT3.200 53.18,2.9 53.19,2.91 53.19,3.38 54.07,4.26 54.07,5.01 v1(53.56,5.52)
SPI_PCH_SNIFF_IO1: length 29.3
  TOP w0.104: UT4.B13 v1(51.43,25.57)
  L8-SIG w0.076: v1(51.43,25.57) 51.89,25.11 51.89,24.54 53.29,23.14 53.29,22.3 54.22,21.37 54.22,17.61 53.82,17.21 53.82,16.46 52.42,15.06 52.42,13.33 53.66,12.09 53.66,8.66 53.12,8.13 53.12,4.12 53.31,3.94 54.37,3.94 v1(54.59,4.16)
  BOTTOM w0.112: v1(54.59,4.16) 54.02,3.59 54.02,3.08 53.68,2.73 JT3.202
SPI_PCH_SNIFF_IO2: length 28.9
  TOP w0.127: UT4.C12 v1(52.38,26.52)
  L8-SIG w0.076: v1(52.38,26.52) 52.76,26.14 54.45,26.14 54.81,25.79 54.81,25.53 55.44,24.9 55.44,21.77 55.89,21.32 55.89,12.27 55.21,11.59 55.21,8.08 55.38,7.92 55.38,5.43 54.97,5.02 54.97,3.94 v1(54.65,3.62)
  BOTTOM w0.112: JT3.204 54.18,2.81 54.3,2.93 54.3,3.23 54.65,3.58 v1(54.65,3.62)
SPI_PCH_SNIFF_IO3: length 30.9
  TOP w0.127: UT4.D12 v1(52.38,27.52)
  L8-SIG w0.076: v1(55.62,4.45) 55.62,8.03 56.31,8.72 56.31,10.93 55.95,11.28 55.95,11.98 56.76,12.8 56.76,14.74 56.28,15.22 56.28,21.69 56.54,21.95 56.54,24.92 54.43,27.02 52.88,27.02 v1(52.38,27.52)
  BOTTOM w0.112: v1(55.62,4.45) 55.42,4.45 55.03,4.07 55.03,3.46 54.68,3.11 JT3.206
TP_C5_DNU_1: length 0.6
  TOP w0.127: UT7.D23 v1(20.38,26.41)
TP_C5_DNU_4: length 0.6
  TOP w0.127: UT7.B2 v1(18.78,8.81)
TP_C5_DNU_5: length 0.6
  TOP w0.127: UT7.A2 v1(17.98,8.81)
TP_C5_FPGA_AS_DATA3: length 0.6
  TOP w0.127: UT7.AB6 v1(35.58,12.01)
TP_C5_FPGA_AS_NCSO: length 0.6
  TOP w0.127: UT7.AA6 v1(34.78,12.01)
TP_C5_GPIO4A_IO43: length 0.6
  TOP w0.127: UT7.AE17 37.98,21.61 v1(37.98,21.61)
TP_GXB_TX_L1_DN: length 0.6
  TOP w0.127: UT7.Y1 v1(33.98,8.01)
TP_GXB_TX_L1_DP: length 0.6
  TOP w0.127: UT7.Y2 v1(33.98,8.81)
TP_GXB_TX_L2_DN: length 0.6
  TOP w0.127: UT7.T1 v1(29.98,8.01)
TP_GXB_TX_L3_DP: length 0.6
  TOP w0.127: UT7.M2 v1(27.58,8.81)
TP_GXB_TX_L5_DN: length 0.6
  TOP w0.127: UT7.D1 v1(20.38,8.01)
TP_GXB_TX_L5_DP: length 0.6
  TOP w0.127: UT7.D2 v1(20.38,8.81)
TP_HPS_GPI0: length 0.6
  TOP w0.127: UT7.M25 v1(26.78,28.01)
TP_HPS_GPI1: length 0.6
  TOP w0.127: UT7.K27 25.18,29.61 v1(25.16,29.61)
TP_HPS_GPI4: length 0.6
  TOP w0.127: UT7.R28 v1(29.98,30.41)
TP_HPS_GPI5: length 0.6
  TOP w0.127: UT7.P26 v1(28.38,28.81)
TP_HPS_GPI6: length 0.6
  TOP w0.127: UT7.T17 v1(30.78,21.61)
TP_HPS_GPI9: length 0.6
  TOP w0.127: v1(34,28.81) 33.98,28.81 UT7.Y26
TP_HPS_GPI11: length 0.6
  TOP w0.127: UT7.U16 v1(31.58,20.81)
TP_HPS_GPI12: length 0.6
  TOP w0.127: UT7.AC27 v1(36.38,29.61)
TP_HPS_GPI13: length 0.6
  TOP w0.127: UT7.V24 32.37,27.2 v1(32.41,27.2)
TP_M10_CRC_ERROR: length 0.7
  TOP w0.127: UT4.C5 v1(60.38,26.52)
TP_M10_DEV_OE: length 0.8
  TOP w0.127: UT4.B8 57.3,25.6 v1(57.5,25.6)
TP_TRC_HPS_TRACE32_D5: length 0.6
  TOP w0.127: UT7.J18 v1(24.38,22.41)
TP_TRC_HPS_TRACE32_D6: length 1.1
  TOP w0.127: v1(17.37,22.52) 17.65,22.8 17.66,22.8 17.66,22.81 UT7.A19
TP_TRC_HPS_TRACE32_D7: length 0.6
  TOP w0.127: UT7.C18 v1(19.58,22.41)
TP_USB2B_PWREN: length 0.4
  BOTTOM w0.112: R412.2 v1(64.46,15.65)
TP_V_M_BMC_DDR3_ODT1: length 0.6
  TOP w0.127: UT7.G26 22.8,28.79 v1(22.8,28.81)
TP_V_M_CE1: length 0.6
  TOP w0.127: U2.J9 v1(16.53,40.83)
TP_V_M_CE1_1: length 0.6
  TOP w0.127: U3.J9 v1(26.37,40.81)
TP_V_M_CE1_2: length 0.6
  TOP w0.127: U4.J9 v1(36.15,40.76)
TP_V_M_CS1_1_N: length 0.6
  TOP w0.127: U3.L1 v1(33.57,42.41)
TP_V_M_CS1_2_N: length 0.6
  TOP w0.127: U4.L1 v1(43.35,42.36)
TP_V_M_CS1_N: length 0.6
  TOP w0.127: U2.L1 v1(23.73,42.43)
TP_V_M_ODT1: length 0.6
  TOP w0.127: U2.J1 v1(23.73,40.83)
TP_V_M_ODT1_1: length 0.6
  TOP w0.127: U3.J1 v1(33.57,40.81)
TP_V_M_ODT1_2: length 0.6
  TOP w0.127: U4.J1 v1(43.35,40.76)
TP_V_M_ZQ1: length 0.6
  TOP w0.127: U2.L9 v1(16.53,42.43)
TP_V_M_ZQ1_1: length 0.6
  TOP w0.127: U3.L9 v1(26.37,42.41)
TP_V_M_ZQ1_2: length 0.6
  TOP w0.127: U4.L9 v1(36.15,42.36)
TRC_HPS_TRACE32_D0: length 22.7
  TOP w0.089: UT7.A22 v1(17.97,24.8)
  TOP w0.104: RT8.2 6.83,39.96 6.57,39.7 v1(6.57,39.63)
  L10-SIG w0.076: v1(6.57,39.63) 6.57,34.16 7.74,32.99 8.16,32.99 10.33,30.81 10.33,29.63 11.89,28.07 13.63,28.07 16.64,25.06 17.71,25.06 v1(17.97,24.8)
TRC_HPS_TRACE32_D0_R: length 2.5
  TOP w0.104: RT8.1 6.83,41.55 6.54,41.83 J4.14
TRC_HPS_TRACE32_D1: length 24.9
  TOP w0.104: RT7.2 5.94,39.68 v1(6.04,39.58)
  TOP w0.127: UT7.B21 v1(18.78,24.81)
  L10-SIG w0.076: v1(6.04,39.58) 6.04,39.6 6.42,39.98 6.71,39.98 7.49,39.21 7.49,33.51 7.79,33.2 8.4,33.2 9.7,31.91 12.11,31.91 12.34,31.68 12.34,29.93 14.19,28.07 14.19,27.89 16.66,25.43 18.15,25.43 v1(18.78,24.81)
TRC_HPS_TRACE32_D1_R: length 2.7
  TOP w0.127: RT7.1 5.27,41.78 J4.16
TRC_HPS_TRACE32_D2: length 24.2
  TOP w0.089: 17.62,24.41 UT7.A21
  TOP w0.104: v1(4.88,39.63) 5.05,39.79 RT6.2 ; 17.62,24.41 17.6,24.41 v1(17.37,24.64)
  L10-SIG w0.076: v1(4.88,39.63) 5.38,39.14 5.38,38.64 6.34,37.67 6.34,33.64 7.19,32.8 8.08,32.8 8.91,31.97 8.91,30.06 10.89,28.07 11.5,28.07 11.75,27.82 13.51,27.82 16.68,24.64 v1(17.37,24.64)
TRC_HPS_TRACE32_D2_R: length 2.8
  TOP w0.127: J4.18 4,42.47 4.5,41.96 4.5,41.66 RT6.1
TRC_HPS_TRACE32_D3: length 39.5
  TOP w0.104: v1(3.95,40.87) 3.64,41.18 RT2.2
  TOP w0.127: v1(25.16,22.41) 25.18,22.41 UT7.K18
  L10-SIG w0.076: v1(25.16,22.41) 24.75,22 16.83,22 16.67,22.17 16.66,22.17 15.98,22.84 13.91,22.84 13.48,23.27 13.48,27.03 13.23,27.29 11.63,27.29 11.27,27.64 9.87,27.64 9.53,27.98 7.91,27.98 6.9,28.99 5.05,28.99 3.56,30.48 3.56,40.49 v1(3.95,40.87)
TRC_HPS_TRACE32_D3_R: length 2.5
  TOP w0.104: RT2.1 2.32,41.25 2.73,41.67 J4.20
TRC_TRACE32_CLK: length 23.5
  TOP w0.104: RT9.2 7.71,39.66 7.82,39.55 v1(7.82,39.55)
  TOP w0.127: UT7.C21 v1(19.58,24.81)
  L10-SIG w0.076: v1(7.82,39.55) 8.38,39 8.38,33.59 9.85,32.11 12.31,32.11 12.59,31.83 12.59,30.03 14.53,28.09 14.53,27.9 16.77,25.66 18.23,25.66 18.69,25.2 19.18,25.2 v1(19.58,24.81)
TRC_TRACE32_CLK_R: length 2.7
  TOP w0.104: RT9.1 7.33,41.5 7.33,41.76 7.81,42.24 J4.12
ULPI_USBPHY_PCH_CLKOUT: length 35.2
  TOP w0.112: R8A57.2 51.89,12.86 51.32,12.28 51.32,11.39 51.45,11.27 51.45,10.28 51.71,10.02 v1(51.71,9.84)
  TOP w0.127: UT7.G4 v1(22.78,10.41)
  L10-SIG w0.076: v1(51.71,9.84) 46.53,9.84 45.94,10.42 43.38,10.42 42.11,9.15 34.56,9.15 34.41,9.3 34.41,9.66 34.11,9.96 23.22,9.96 v1(22.78,10.41)
ULPI_USBPHY_PCH_CLKOUT_R: length 1.6
  TOP w0.104: R8A57.1 54.29,12.12 54.32,12.12 54.38,12.07 U8A6.1
ULPI_USBPHY_PCH_DATA<0>: length 38.3
  TOP w0.104: v1(51.99,12.05) 51.99,11.47 52.13,11.33 R8A55.2
  TOP w0.127: UT7.C10 v1(19.58,15.21)
  L10-SIG w0.076: v1(51.99,12.05) 52.29,12.35 52.29,13.65 51.73,14.2 50.46,14.2 49.73,13.47 41.83,13.47 41.57,13.21 35.93,13.21 35.5,12.78 24.17,12.78 23.95,13.01 23.36,13.01 22.87,13.51 22.87,13.96 21.99,14.84 19.95,14.84 v1(19.58,15.21)
ULPI_USBPHY_PCH_DATA<1>: length 35.1
  TOP w0.104: R8A53.2 52.11,10.57 52.09,10.59 v1(52.07,10.59)
  TOP w0.127: UT7.F5 v1(21.98,11.21)
  L10-SIG w0.076: v1(21.98,11.21) 22.39,10.8 34.18,10.8 34.36,10.62 34.36,10.22 34.59,9.99 42.27,9.99 42.93,10.66 46.13,10.66 46.6,10.2 48.27,10.2 48.35,10.27 48.35,10.9 48.42,10.98 48.58,10.98 48.65,10.9 48.65,10.27 48.73,10.2 49.85,10.2 49.93,10.27 49.93,10.8 50,10.88 50.16,10.88 50.23,10.8 50.23,10.27 50.31,10.2 51.64,10.2 52.03,10.59 v1(52.07,10.59)
ULPI_USBPHY_PCH_DATA<2>: length 44.1
  TOP w0.104: v1(52.83,9.23) 52.8,9.25 52.8,9.67 R8A51.2
  TOP w0.127: UT7.C9 v1(19.58,14.41)
  L10-SIG w0.076: v1(52.83,9.23) 53.43,9.23 54.5,10.29 54.5,11.74 54.35,11.89 53.31,11.89 53.03,11.61 51.78,11.61 51.61,11.78 51.61,12.23 51.96,12.58 51.96,13.54 51.63,13.87 50.49,13.87 49.87,13.25 42.09,13.25 41.24,12.4 36.06,12.4 35.88,12.58 24.12,12.58 23.92,12.78 22.9,12.78 22.61,13.07 22.61,13.66 22.29,13.98 20.01,13.98 v1(19.58,14.41)
ULPI_USBPHY_PCH_DATA<3>: length 40
  TOP w0.104: v1(51.66,6.89) 51.66,7.5 51.91,7.75 52.23,7.75 52.68,8.2 R8A49.2
  TOP w0.127: UT7.C4 v1(19.58,10.41)
  L10-SIG w0.076: v1(19.58,10.41) 19.58,10.19 19.23,9.84 19.23,7.82 20.18,6.86 21.48,6.86 21.67,6.68 22.16,6.68 22.44,6.97 30.09,6.97 30.47,6.58 33.83,6.58 34.18,6.23 42.97,6.23 44.04,7.3 50.18,7.3 50.59,6.89 v1(51.66,6.89)
ULPI_USBPHY_PCH_DATA<4>: length 41.2
  TOP w0.127: UT7.C8 v1(19.57,13.6)
  L10-SIG w0.076: v1(54.08,11.36) 53.71,11.36 53.58,11.23 51.71,11.23 51.38,11.56 51.38,12.32 51.66,12.6 51.66,13.26 51.35,13.56 50.48,13.56 49.96,13.04 48.37,13.04 48.06,12.73 48.06,12.6 47.82,12.36 47.47,12.36 47.25,12.58 47.25,12.71 46.92,13.04 42.36,13.04 41.45,12.12 37.86,12.12 37.38,11.64 36.49,11.64 35.76,12.38 24.05,12.38 23.84,12.58 22.73,12.58 22.12,13.19 22.12,13.21 20.85,13.21 20.46,13.6 v1(19.57,13.6)
  BOTTOM w0.112: v1(54.08,11.36) 54.76,10.68 R8A47.2
ULPI_USBPHY_PCH_DATA<5>: length 37.6
  TOP w0.104: v1(52.11,7.35) 52.39,7.35 52.5,7.45 R8A44.2
  TOP w0.127: UT7.D4 v1(20.38,10.41)
  L10-SIG w0.076: v1(20.38,10.41) 19.93,9.96 19.93,7.75 20.54,7.14 21.51,7.14 21.76,6.9 22.07,6.9 22.39,7.22 30.15,7.22 30.53,6.84 33.88,6.84 34.26,6.46 42.03,6.46 43.07,7.5 50.41,7.5 50.56,7.35 v1(52.11,7.35)
ULPI_USBPHY_PCH_DATA<6>: length 45.4
  TOP w0.104: R8A45.2 52.74,6.18 52.84,6.08 54.2,6.08 54.55,6.43 v1(54.55,6.51)
  TOP w0.127: UT7.C7 v1(19.58,12.81)
  L10-SIG w0.076: v1(54.55,6.51) 54.69,6.64 54.69,6.75 53.58,7.86 53.58,7.97 54.07,8.46 54.07,8.57 53.96,8.67 53.85,8.67 53.36,8.19 53.26,8.19 52.44,9 52.44,10.79 52.23,11.01 51.6,11.01 50.81,11.81 50.8,11.81 50.77,11.84 49.65,11.84 49.45,11.65 46.33,11.65 45.22,12.76 42.56,12.76 41.7,11.89 38.07,11.89 37.51,11.33 36.14,11.33 35.81,11.67 34.59,11.67 34.36,11.89 24.18,11.89 23.72,12.35 21.15,12.35 20.84,12.67 20.84,12.84 20.52,13.15 19.92,13.15 v1(19.58,12.81) 19.6,12.81
ULPI_USBPHY_PCH_DATA<7>: length 40.9
  TOP w0.104: R8A43.2 58.23,5.27 v1(58.23,4.85)
  TOP w0.127: UT7.F4 v1(21.98,10.41)
  L10-SIG w0.076: v1(21.98,10.41) 22.42,9.96 22.42,9.38 22.57,9.23 34.05,9.23 34.38,8.9 34.38,8.66 34.69,8.36 39.87,8.36 40.18,8.67 43.63,8.67 43.81,8.49 45.1,8.49 45.43,8.82 51.89,8.82 52.55,8.16 52.55,7.98 55.49,5.03 58.05,5.03 v1(58.23,4.85)
ULPI_USBPHY_PCH_DIR: length 38.2
  TOP w0.127: UT7.E5 v1(21.18,11.21)
  L10-SIG w0.076: v1(21.18,11.21) 21.56,10.83 21.56,8.63 21.8,8.39 34.26,8.39 34.56,8.08 40.17,8.08 40.45,8.36 43.33,8.36 43.77,7.92 49.59,7.92 50.11,8.44 v1(51.68,8.44)
  BOTTOM w0.112: R8A61.2 53.46,9.04 52.85,8.44 v1(51.68,8.44)
ULPI_USBPHY_PCH_DIR_R: length 4.1
  TOP w0.104: v1(54.5,12.59) 54.5,13.11 54.81,13.42 55.86,13.42 56,13.28 U8A6.31
  BOTTOM w0.112: R8A61.1 54.1,12.59 v1(54.5,12.59)
ULPI_USBPHY_PCH_NXT: length 42.2
  TOP w0.112: v1(51.37,7.75) 51.67,8.05 51.96,8.05 52.19,8.29 52.19,9.93 51.68,10.43 51.68,11.36 51.56,11.49 51.56,12.16 51.83,12.43 52.15,12.43 52.3,12.27 52.48,12.27 R8A56.2
  TOP w0.127: UT7.D5 v1(20.38,11.21)
  L10-SIG w0.076: v1(51.37,7.75) 50.93,8.19 50.45,8.19 49.96,7.7 43.68,7.7 43.5,7.88 41.04,7.88 40.5,7.34 33.93,7.34 33.55,7.73 32.68,7.73 32.6,7.64 20.95,7.64 20.83,7.77 20.83,10.59 20.38,11.04 v1(20.38,11.21)
ULPI_USBPHY_PCH_NXT_R: length 1.5
  TOP w0.104: U8A6.2 54.6,11.57 54.43,11.74 54.3,11.74 53.94,12.1 R8A56.1
ULPI_USBPHY_PCH_R_DATA<0>: length 1.6
  TOP w0.104: R8A55.1 53.47,11.33 53.83,10.98 54.29,10.98 54.38,11.07 U8A6.3
ULPI_USBPHY_PCH_R_DATA<1>: length 1.4
  TOP w0.104: R8A53.1 53.48,10.57 U8A6.4
ULPI_USBPHY_PCH_R_DATA<2>: length 1.4
  TOP w0.104: R8A51.1 53.98,9.81 54.24,10.07 U8A6.5
ULPI_USBPHY_PCH_R_DATA<3>: length 1.6
  TOP w0.104: U8A6.6 54.07,9.57 53.59,9.09 R8A49.1
ULPI_USBPHY_PCH_R_DATA<4>: length 1.5
  TOP w0.104: v1(54.15,9.1) 54.18,9.07 U8A6.7
  BOTTOM w0.112: v1(54.15,9.1) 54.15,9.21 54.3,9.37 R8A47.1
ULPI_USBPHY_PCH_R_DATA<5>: length 2.1
  TOP w0.104: U8A6.9 54.76,7.92 54.28,7.45 R8A44.1
ULPI_USBPHY_PCH_R_DATA<6>: length 3.2
  TOP w0.104: R8A45.1 54.02,6.71 54.43,7.12 55.7,7.12 56,7.42 U8A6.10
ULPI_USBPHY_PCH_R_DATA<7>: length 2
  TOP w0.104: R8A43.1 57.83,6.88 57.83,7.25 57.49,7.59 U8A6.13
ULPI_USBPHY_PCH_STP: length 62.9
  TOP w0.104: v1(57.37,14.03) 57.3,13.95 57.22,13.95 57,13.73 R8A64.2 56.86,13.49 57,13.36 U8A6.29
  TOP w0.127: UT7.C5 v1(19.58,11.21)
  L8-SIG w0.076: v1(57.37,14.03) 57.42,14.03 57.89,13.56 57.89,5.83 57.37,5.31 57.37,3.58 57.48,3.47 v1(57.86,3.47)
  L10-SIG w0.076: v1(19.58,11.21) 19.22,10.85 19.22,10.24 18.99,10.01 18.64,10.01 18.38,9.76 18.38,7.7 18.6,7.49 19.26,7.49 20.09,6.65 21.39,6.65 21.58,6.46 22.25,6.46 22.5,6.71 30.04,6.71 30.42,6.33 33.67,6.33 33.99,6.01 44.02,6.01 45.1,7.09 50.08,7.09 50.84,6.33 50.84,2.93 51.07,2.7 57.12,2.7 57.85,3.43 57.85,3.47 v1(57.86,3.47)
ULPI_USBPHY_USB2B_CLKOUT: length 52.5
  TOP w0.112: v1(52.9,17.2) 53.18,17.2 53.84,17.86 53.84,19.82 54.81,20.78 R408.2
  TOP w0.127: UT7.B12 v1(19.55,16.83)
  L10-SIG w0.076: v1(19.55,16.83) 19.66,16.95 22.47,16.95 23.18,16.24 23.18,15.73 23.31,15.6 23.67,15.6 24.04,15.24 24.04,14.88 24.12,14.79 28.9,14.79 28.98,14.86 28.98,15.17 29.05,15.25 29.21,15.25 29.28,15.17 29.28,14.86 29.36,14.79 35.32,14.79 35.59,15.06 35.59,15.16 35.2,15.55 35.2,15.66 35.31,15.77 35.42,15.77 35.81,15.38 35.92,15.38 36.02,15.49 36.02,15.59 35.64,15.98 35.64,16.09 35.74,16.2 35.85,16.2 36.24,15.81 36.35,15.81 36.45,15.92 36.45,16.03 36.07,16.41 36.07,16.52 36.17,16.63 36.28,16.63 36.67,16.24 36.78,16.24 36.98,16.44 42.21,16.44 42.49,16.72 44.77,16.72 45.18,16.31 46.26,16.31 46.33,16.24 46.33,15.52 46.41,15.45 46.56,15.45 46.64,15.52 46.64,16.24 46.71,16.31 46.87,16.31 46.94,16.24 46.94,15.52 47.02,15.45 47.17,15.45 47.25,15.52 47.25,16.24 47.32,16.31 47.48,16.31 47.55,16.24 47.55,15.52 47.63,15.45 47.78,15.45 47.86,15.52 47.86,16.24 47.93,16.31 48.09,16.31 48.16,16.24 48.16,15.52 48.24,15.45 48.39,15.45 48.47,15.52 48.47,16.24 48.54,16.31 50.77,16.31 51.5,17.05 52.75,17.05 v1(52.9,17.2)
ULPI_USBPHY_USB2B_CLKOUT_R: length 2
  TOP w0.127: R408.1 56.99,20.78 57.17,20.6 57.17,20.15 57.5,19.82 EU12.1
ULPI_USBPHY_USB2B_DATA<0>: length 53.2
  TOP w0.112: R406.2 55.39,19.31 v1(54.96,19.74)
  TOP w0.127: UT7.D14 20.38,18.41 v1(20.38,18.41)
  L10-SIG w0.076: v1(54.96,19.74) 55.92,19.74 56.13,19.94 56.13,20.6 55.82,20.91 55.56,20.91 55.49,20.83 55.49,20.3 55.41,20.22 55.26,20.22 55.18,20.3 55.18,20.83 55.11,20.91 54.95,20.91 54.88,20.83 54.88,20.3 54.8,20.22 54.65,20.22 54.57,20.3 54.57,20.83 54.5,20.91 54.34,20.91 54.27,20.83 54.27,20.3 54.19,20.22 54.04,20.22 53.96,20.3 53.96,20.83 53.89,20.91 53.73,20.91 53.66,20.83 53.66,20.3 53.58,20.22 53.43,20.22 53.35,20.3 53.35,20.83 53.28,20.91 53.04,20.91 52.97,20.83 52.97,20.35 52.89,20.27 52.74,20.27 52.66,20.35 52.66,20.83 52.58,20.91 50.67,20.91 50.59,20.83 50.59,19.44 50.51,19.36 50.36,19.36 50.29,19.44 50.29,19.89 50.21,19.97 50.06,19.97 49.98,19.89 49.98,19.44 49.9,19.36 49.75,19.36 49.68,19.44 49.68,19.89 49.6,19.97 49.45,19.97 49.37,19.89 49.37,19.44 49.29,19.36 49.14,19.36 49.07,19.44 49.07,19.89 48.99,19.97 48.79,19.97 48.22,19.4 46.7,19.4 46.62,19.48 46.62,19.84 46.54,19.92 46.39,19.92 46.31,19.84 46.31,19.48 46.24,19.4 46.09,19.4 46.01,19.48 46.01,19.84 45.93,19.92 45.78,19.92 45.71,19.84 45.71,19.48 45.63,19.4 45.48,19.4 45.4,19.48 45.4,19.84 45.32,19.92 45.17,19.92 45.1,19.84 45.1,19.48 45.02,19.4 43.8,19.4 43.73,19.48 43.73,19.84 43.65,19.92 43.5,19.92 43.42,19.84 43.42,19.48 43.35,19.4 43.03,19.4 42.89,19.54 41.29,19.54 40.91,19.16 35.88,19.16 35.5,18.78 20.75,18.78 v1(20.38,18.41)
